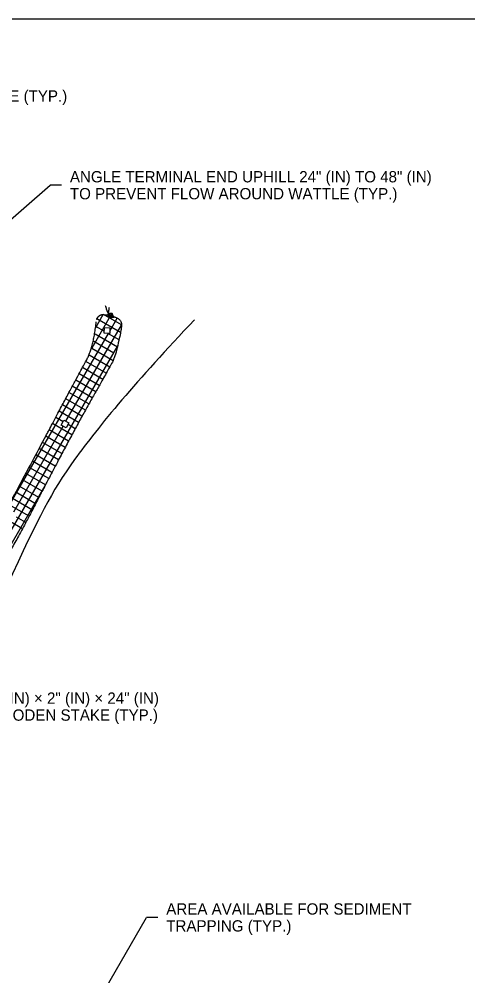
# Model space of a CAD drawing. Extents: x 99862 to 103680, y 99470 to 102076.
# Drawn here: x 101092 to 101727, y 100721 to 102076 of the extents above; entities that cross this region are included whole.
import ezdxf

# ---------------------------------------------------------------- set-up
doc = ezdxf.new("R2010")
doc.units = 0
for name, color, linetype in [('Level 1', 7, 'Continuous'), ('Level 10', 7, 'Continuous'), ('Level 15', 7, 'Continuous'), ('Level 20', 7, 'Continuous'), ('Level 4', 7, 'Continuous'), ('Level 9', 7, 'Continuous')]:
    doc.layers.add(name, color=color, linetype=linetype)

msp = doc.modelspace()

# ---------------------------------------------------------------- linework, layer by layer
at = {"layer": 'Level 1'}
msp.add_lwpolyline([(99862, 99999.5), (103151, 99999.5), (103151, 102075.5), (99862, 102075.5)], close=True, dxfattribs=at)
at = {"layer": 'Level 10'}
for points in [[(101214.2, 101670.1), (101218.1, 101656.4), (101223, 101656.8), (101228.2, 101653.1), (101221, 101652.4), (101219.3, 101654.2)], [(101219.3, 101654.2), (101217.5, 101656), (101219.4, 101656.7), (101227.3, 101654), (101223.4, 101652.9), (101217.8, 101655.8), (101220.2, 101667.7)], [(101202, 101650.5), (101204.2, 101654.7), (101209.7, 101657.7), (101216.7, 101655.9), (101223.8, 101660.6), (101224.5, 101654.6), (101231.1, 101652.6), (101237.4, 101647.2), (101236.9, 101637.5), (101236.6, 101634.8), (101228.5, 101597.6), (101219.1, 101580), (101181.2, 101513.4), (101139.8, 101435.9), (101087, 101333.5), (101049.9, 101275), (101036, 101254), (101011, 101229.8), (101001.1, 101230.8), (100994.9, 101234.5), (100983.6, 101230.1), (100989.4, 101240.9), (100984.5, 101248.6), (100985.9, 101255.8), (101011.9, 101272.9), (101018, 101275.8), (101103.3, 101434.4), (101175.3, 101570.3), (101197.9, 101610.7), (101201.4, 101646.6)]]:
    msp.add_open_spline(points, degree=2, dxfattribs=at)
at = {"layer": 'Level 15'}
for p, q in [((100995.9, 101717.8), (101136.2, 101840.3)), ((101152.2, 101840.3), (101136.2, 101840.3)), ((101164.2, 100615.5), (101272.6, 100803.3)), ((101164.2, 100615.5), (101272.6, 100803.3)), ((101288.6, 100803.3), (101272.6, 100803.3)), ((101288.6, 100803.3), (101272.6, 100803.3))]:
    msp.add_line(p, q, dxfattribs=at)
at = {"layer": 'Level 4'}
for points in [[(101212.5, 101630.6), (101213, 101638.6), (101220.9, 101638.2), (101220.5, 101630.2)], [(101152, 101500.4), (101155.7, 101507.4), (101162.8, 101503.7), (101159, 101496.6)]]:
    msp.add_lwpolyline(points, close=True, dxfattribs=at)
msp.add_open_spline([(101340.4, 101649.8), (101259, 101563.8), (101150.9, 101434.3), (101122.5, 101374.4), (101074.1, 101271.7)], degree=3, dxfattribs=at)
at = {"layer": 'Level 9'}
for p, q in [((101195.5, 101610), (101223.7, 101658.8)), ((101200.7, 101639), (101211.2, 101657.2)), ((101235.9, 101631.6), (101202.4, 101651)), ((101237.2, 101642.4), (101211.7, 101657.1)), ((101220.7, 101633.6), (101231.3, 101652)), ((101158.5, 101505.9), (101237.1, 101642.1)), ((101212.7, 101633.5), (101200.8, 101640.3)), ((101071, 101374.4), (101218.8, 101630.3)), ((101231.4, 101611.1), (101199.8, 101629.4)), ((101233.7, 101621.3), (101218.1, 101630.3)), ((101012.2, 101232.5), (101231.8, 101612.9)), ((101225.2, 101591.6), (101195.1, 101609)), ((101226.3, 101602.5), (101198, 101618.8)), ((101220.5, 101582.8), (101191.3, 101599.6)), ((101210.7, 101565.3), (101181.9, 101582)), ((101215.6, 101574), (101186.7, 101590.7)), ((101205.8, 101556.6), (101177.1, 101573.2)), ((101195.9, 101539.2), (101167.6, 101555.6)), ((101200.8, 101547.9), (101172.4, 101564.4)), ((101191, 101530.5), (101162.9, 101546.7)), ((101181.3, 101513), (101153.5, 101529.1)), ((101186.2, 101521.8), (101158.2, 101537.9)), ((101176.5, 101504.2), (101148.8, 101520.2)), ((101167, 101486.6), (101139.4, 101502.6)), ((101154.6, 101505.3), (101144.1, 101511.4)), ((101171.7, 101495.4), (101161.5, 101501.3)), ((101084.6, 101377.9), (101154.5, 101499)), ((101162.2, 101477.8), (101134.7, 101493.7)), ((101152.8, 101460.2), (101125.3, 101476)), ((101157.5, 101469), (101130, 101484.9)), ((101148.1, 101451.3), (101120.6, 101467.2)), ((101138.8, 101433.6), (101111.2, 101449.5)), ((101143.5, 101442.5), (101115.9, 101458.4)), ((101129.6, 101415.9), (101101.8, 101431.9)), ((101134.2, 101424.7), (101106.5, 101440.7)), ((101124.9, 101407), (101097.1, 101423.1)), ((101039, 101259), (101129.1, 101415)), ((101115.7, 101389.2), (101087.7, 101405.4)), ((101120.3, 101398.1), (101092.4, 101414.2)), ((101111.1, 101380.3), (101082.9, 101396.6)), ((101106.5, 101371.4), (101078.2, 101387.8)), ((101097.1, 101353.8), (101068.7, 101370.1)), ((101101.8, 101362.6), (101088.7, 101370.2))]:
    msp.add_line(p, q, dxfattribs=at)

# ---------------------------------------------------------------- texts
at = {"layer": 'Level 20'}
for s, p in [('CONTOUR LINE (TYP.)', (100931, 101958.7)), ('2" (IN) × 2" (IN) × 24" (IN) ', (101046.3, 101105.9)), ('WOODEN STAKE (TYP.)', (101046.3, 101081.9)), ('AREA AVAILABLE FOR SEDIMENT ', (101300.6, 100807.3)), ('TRAPPING (TYP.)', (101300.6, 100783.3))]:
    msp.add_text(s, height=16, rotation=360, dxfattribs=at).set_placement(p)
for s, p in [('ANGLE TERMINAL END UPHILL 24" (IN) TO 48" (IN)', (101164.2, 101844.3)), ('TO PREVENT FLOW AROUND WATTLE (TYP.)', (101164.2, 101820.3))]:
    msp.add_text(s, height=16, dxfattribs=at).set_placement(p)

doc.saveas('drawing.dxf')
